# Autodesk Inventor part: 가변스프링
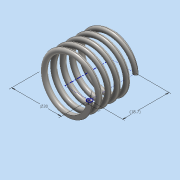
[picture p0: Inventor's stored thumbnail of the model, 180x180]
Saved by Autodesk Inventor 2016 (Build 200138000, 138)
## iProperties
Created: 2019-01
Part Number: 가변스프링
Material: 스테인레스 스틸
Document SubType Name: Modeling
Designer: 3sil_cad018
Density: 8 g/cm^3
Appearance: 반연마
Author: 3sil_cad018
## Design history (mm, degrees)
sketch "스케치1"
  geometry: L1 (0, 0)-(10, 0); L2 (10, 0)-(10, 18.7); L3 (10, 18.7)-(0, 18.7); L4 (0, 18.7)-(0, 0); C1 r 1 at (10, 0)
  constraints: 8 end point, 2 parallel, 1 centre point, 1 coincident, 1 horizontal, 1 perpendicular
  dimensions: "d0" = 20 diameter of L2 L4; "d1" = 18.7 distance of L1.end L2.end (derived); "d2" = 2 diameter of C1
feature "코일1" pitch "d3" = 10; turns "d5" = 5; dims "d4" = 18.7 (= d1), "d6" = 0, angle "d7" = 90 deg, angle "d8" = 90 deg, "d9" = 0, "d10" = 0
sketch "스케치2"
  geometry: L1 (-11, 0)-(-9, 0) reference; 1 further point
  constraints: 1 horizontal alignment
extrude "돌출1" cut sketch "스케치2" stored distance "d11" = 10; taper "d12" = 0 deg
node "작업 평면1"
sketch "스케치3"
  geometry: L1 (1, 0)-(-1, 0) reference; 1 further point
  constraints: 1 horizontal alignment
extrude "돌출2" cut sketch "스케치3" stored distance "d14" = 10; taper "d15" = 0 deg
node "솔리드1"
node "절단 모서리 투영1"
node "절단 모서리 투영2"
other parameters: "d13" = 90 deg
